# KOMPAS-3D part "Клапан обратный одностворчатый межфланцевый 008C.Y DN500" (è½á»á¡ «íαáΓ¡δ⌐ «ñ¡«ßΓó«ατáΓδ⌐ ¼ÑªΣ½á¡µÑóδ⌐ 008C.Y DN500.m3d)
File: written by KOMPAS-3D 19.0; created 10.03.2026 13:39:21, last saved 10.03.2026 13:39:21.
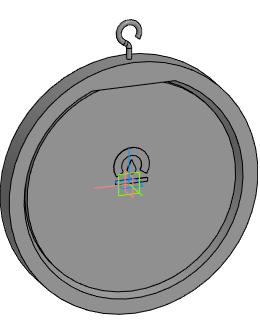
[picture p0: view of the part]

Document properties: Автор: Евгений; Полное имя файла: E:\Dendor\3D для проектировщиков\5.1 Тип 008C. Клапан обратный одностворчатый межфланцевый\stp_Клапан обратный одностворчатый межфланцевый 008C.Y\Клапан обратный одностворчатый межфланцевый 008C.Y DN500.m3d

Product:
- Part/product: Клапан обратный одностворчатый межфланцевый 008C.Y DN500

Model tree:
1. Операция без истории:1  (labels: Клапан обратный одностворчатый межфланцевый 008C.Y DN500)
